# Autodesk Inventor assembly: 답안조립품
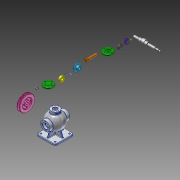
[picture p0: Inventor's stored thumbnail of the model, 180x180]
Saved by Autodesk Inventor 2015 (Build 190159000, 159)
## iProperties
Created: 2025-08
Part Number: 답안조립품
Document SubType Name: Assembly
Designer: user
Author: user
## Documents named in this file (15)
- C:\Users\user\Desktop\750808V1005\답안조립품.iam
- C:\Users\user\Desktop\750808V1005\본체.ipt
- C:\Users\user\Desktop\750808V1005\가져온 구성요소\V-벨트풀리\V-벨트풀리.ipt
- C:\Users\user\Desktop\750808V1005\가져온 구성요소\너트 M8\너트 M8.ipt
- C:\Users\user\Desktop\750808V1005\가져온 구성요소\뒤커버\뒤커버.ipt
- C:\Users\user\Desktop\750808V1005\가져온 구성요소\베어링- 6202\베어링- 6202.ipt
- C:\Users\user\Desktop\750808V1005\가져온 구성요소\볼트 M4 x 12\볼트 M4 x 12.ipt
- C:\Users\user\Desktop\750808V1005\가져온 구성요소\볼트 M4 x 16\볼트 M4 x 16.ipt
- C:\Users\user\Desktop\750808V1005\가져온 구성요소\상부커버\상부커버.ipt
- C:\Users\user\Desktop\750808V1005\가져온 구성요소\슬라이드\슬라이드.ipt
- C:\Users\user\Desktop\750808V1005\가져온 구성요소\앞커버\앞커버.ipt
- C:\Users\user\Desktop\750808V1005\가져온 구성요소\오일실 15 30 7\오일실 15 30 7.ipt
- C:\Users\user\Desktop\750808V1005\가져온 구성요소\칼라\칼라.ipt
- C:\Users\user\Desktop\750808V1005\가져온 구성요소\키 4 x 4 x 12\키 4 x 4 x 12.ipt
- C:\Users\user\Desktop\750808V1005\가져온 구성요소\편심축\편심축.ipt
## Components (1 placed, 1 different names)
1. V-벨트풀리:1
